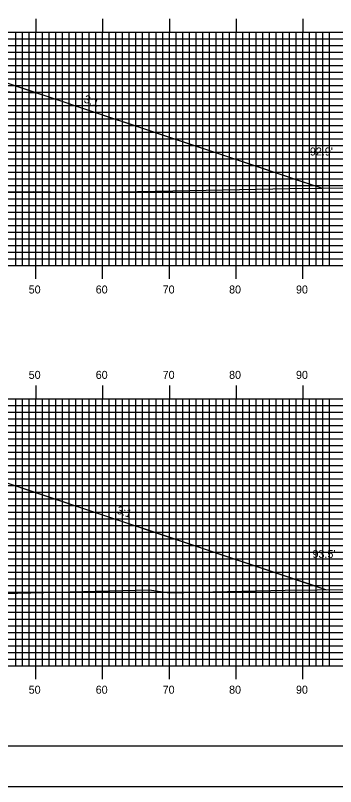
# Model space of a CAD drawing. Extents: x 1756282 to 1756625, y 442591 to 442811.
# Drawn here: x 1756494.5 to 1756542.5, y 442590.5 to 442706.2 of the extents above; entities that cross this region are included whole.
import ezdxf

# ---------------------------------------------------------------- set-up
doc = ezdxf.new("R2010")
doc.units = 0
for name, color, linetype in [('ANNOTATION', 7, 'Continuous'), ('BORDER', 7, 'Continuous'), ('D_Roadway_Centerline', 7, 'Continuous'), ('D_Roadway_SlopeLines', 7, 'Continuous'), ('D_Roadway_SubGrade', 7, 'Continuous'), ('D_Text_Standard', 7, 'Continuous'), ('H_V ANNOTATION', 7, 'Continuous'), ('MAJOR', 7, 'Continuous'), ('MINOR', 7, 'Continuous'), ('PLOT BOUNDARY', 7, 'Continuous'), ('S_Roadway_Centerline', 7, 'Continuous')]:
    doc.layers.add(name, color=color, linetype=linetype)

msp = doc.modelspace()

# ---------------------------------------------------------------- linework, layer by layer
at = {"layer": 'BORDER'}
msp.add_lwpolyline([(1756297.97, 442596.67), (1756617.97, 442596.67), (1756617.97, 442806.67), (1756297.97, 442806.67)], close=True, dxfattribs=at)
at = {"layer": 'D_Roadway_Centerline'}
for points in [[(1756489.74, 442697.22), (1756497.1, 442694.76), (1756497.82, 442694.52), (1756499.66, 442693.9), (1756500.24, 442693.71), (1756509.89, 442690.48), (1756510.11, 442690.41), (1756510.64, 442690.23), (1756510.77, 442690.19), (1756511.07, 442690.09), (1756515.9, 442688.47), (1756522.47, 442686.28), (1756522.59, 442686.23), (1756522.68, 442686.21), (1756531.54, 442683.25), (1756533.88, 442682.46), (1756535.28, 442681.99), (1756535.47, 442681.93), (1756540.47, 442680.26)], [(1756494.45, 442635.67), (1756495.01, 442635.48), (1756495.26, 442635.4), (1756509.79, 442630.54), (1756516.57, 442628.27), (1756524.29, 442625.68), (1756537.31, 442621.32), (1756538.5, 442620.93), (1756541.12, 442620.05)]]:
    msp.add_lwpolyline(points, dxfattribs=at)
at = {"layer": 'D_Roadway_SlopeLines'}
for points in [[(1756489.74, 442697.22), (1756540.47, 442680.26)], [(1756485.73, 442638.59), (1756541.12, 442620.05)]]:
    msp.add_lwpolyline(points, dxfattribs=at)
at = {"layer": 'D_Roadway_SubGrade'}
msp.add_lwpolyline([(1756478.7, 442697.01), (1756478.7, 442697.43), (1756489.74, 442696.97), (1756489.74, 442697.22), (1756497.82, 442694.52), (1756478.7, 442695.18)], close=True, dxfattribs=at)
at = {"layer": 'MAJOR'}
for p, q in [((1756497.57, 442705.67), (1756497.57, 442703.67)), ((1756507.57, 442705.67), (1756507.57, 442703.67)), ((1756517.57, 442705.67), (1756517.57, 442703.67)), ((1756527.57, 442705.67), (1756527.57, 442703.67)), ((1756537.57, 442705.67), (1756537.57, 442703.67)), ((1756307.57, 442703.67), (1756587.57, 442703.67)), ((1756307.57, 442703.67), (1756587.57, 442703.67)), ((1756497.57, 442668.67), (1756497.57, 442703.67)), ((1756507.57, 442668.67), (1756507.57, 442703.67)), ((1756517.57, 442668.67), (1756517.57, 442703.67)), ((1756527.57, 442668.67), (1756527.57, 442703.67)), ((1756537.57, 442668.67), (1756537.57, 442703.67)), ((1756307.57, 442698.67), (1756587.57, 442698.67)), ((1756307.57, 442693.67), (1756587.57, 442693.67)), ((1756307.57, 442688.67), (1756587.57, 442688.67)), ((1756307.57, 442683.67), (1756587.57, 442683.67)), ((1756307.57, 442678.67), (1756587.57, 442678.67)), ((1756307.57, 442673.67), (1756587.57, 442673.67)), ((1756307.57, 442668.67), (1756587.57, 442668.67)), ((1756307.57, 442668.67), (1756587.57, 442668.67)), ((1756497.57, 442666.66), (1756497.57, 442668.67)), ((1756507.57, 442666.66), (1756507.57, 442668.67)), ((1756517.57, 442666.66), (1756517.57, 442668.67)), ((1756527.57, 442666.66), (1756527.57, 442668.67)), ((1756537.57, 442666.66), (1756537.57, 442668.67)), ((1756497.57, 442650.67), (1756497.57, 442648.67)), ((1756507.57, 442650.67), (1756507.57, 442648.67)), ((1756517.57, 442650.67), (1756517.57, 442648.67)), ((1756527.57, 442650.67), (1756527.57, 442648.67)), ((1756537.57, 442650.67), (1756537.57, 442648.67)), ((1756307.57, 442648.67), (1756587.57, 442648.67)), ((1756307.57, 442648.67), (1756587.57, 442648.67)), ((1756497.57, 442608.67), (1756497.57, 442648.67)), ((1756507.57, 442608.67), (1756507.57, 442648.67)), ((1756517.57, 442608.67), (1756517.57, 442648.67)), ((1756527.57, 442608.67), (1756527.57, 442648.67)), ((1756537.57, 442608.67), (1756537.57, 442648.67)), ((1756307.57, 442643.67), (1756587.57, 442643.67)), ((1756307.57, 442638.67), (1756587.57, 442638.67)), ((1756307.57, 442633.67), (1756587.57, 442633.67)), ((1756307.57, 442628.67), (1756587.57, 442628.67)), ((1756307.57, 442623.67), (1756587.57, 442623.67)), ((1756307.57, 442618.67), (1756587.57, 442618.67)), ((1756307.57, 442613.67), (1756587.57, 442613.67)), ((1756307.57, 442608.67), (1756587.57, 442608.67)), ((1756307.57, 442608.67), (1756587.57, 442608.67)), ((1756497.57, 442606.66), (1756497.57, 442608.67)), ((1756507.57, 442606.66), (1756507.57, 442608.67)), ((1756517.57, 442606.66), (1756517.57, 442608.67)), ((1756527.57, 442606.66), (1756527.57, 442608.67)), ((1756537.57, 442606.66), (1756537.57, 442608.67))]:
    msp.add_line(p, q, dxfattribs=at)
at = {"layer": 'MINOR'}
for p, q in [((1756494.57, 442668.67), (1756494.57, 442703.67)), ((1756495.57, 442668.67), (1756495.57, 442703.67)), ((1756496.57, 442668.67), (1756496.57, 442703.67)), ((1756498.57, 442668.67), (1756498.57, 442703.67)), ((1756499.57, 442668.67), (1756499.57, 442703.67)), ((1756500.57, 442668.67), (1756500.57, 442703.67)), ((1756501.57, 442668.67), (1756501.57, 442703.67)), ((1756502.57, 442668.67), (1756502.57, 442703.67)), ((1756503.57, 442668.67), (1756503.57, 442703.67)), ((1756504.57, 442668.67), (1756504.57, 442703.67)), ((1756505.57, 442668.67), (1756505.57, 442703.67)), ((1756506.57, 442668.67), (1756506.57, 442703.67)), ((1756508.57, 442668.67), (1756508.57, 442703.67)), ((1756509.57, 442668.67), (1756509.57, 442703.67)), ((1756510.57, 442668.67), (1756510.57, 442703.67)), ((1756511.57, 442668.67), (1756511.57, 442703.67)), ((1756512.57, 442668.67), (1756512.57, 442703.67)), ((1756513.57, 442668.67), (1756513.57, 442703.67)), ((1756514.57, 442668.67), (1756514.57, 442703.67)), ((1756515.57, 442668.67), (1756515.57, 442703.67)), ((1756516.57, 442668.67), (1756516.57, 442703.67)), ((1756518.57, 442668.67), (1756518.57, 442703.67)), ((1756519.57, 442668.67), (1756519.57, 442703.67)), ((1756520.57, 442668.67), (1756520.57, 442703.67)), ((1756521.57, 442668.67), (1756521.57, 442703.67)), ((1756522.57, 442668.67), (1756522.57, 442703.67)), ((1756523.57, 442668.67), (1756523.57, 442703.67)), ((1756524.57, 442668.67), (1756524.57, 442703.67)), ((1756525.57, 442668.67), (1756525.57, 442703.67)), ((1756526.57, 442668.67), (1756526.57, 442703.67)), ((1756528.57, 442668.67), (1756528.57, 442703.67)), ((1756529.57, 442668.67), (1756529.57, 442703.67)), ((1756530.57, 442668.67), (1756530.57, 442703.67)), ((1756531.57, 442668.67), (1756531.57, 442703.67)), ((1756532.57, 442668.67), (1756532.57, 442703.67)), ((1756533.57, 442668.67), (1756533.57, 442703.67)), ((1756534.57, 442668.67), (1756534.57, 442703.67)), ((1756535.57, 442668.67), (1756535.57, 442703.67)), ((1756536.57, 442668.67), (1756536.57, 442703.67)), ((1756538.57, 442668.67), (1756538.57, 442703.67)), ((1756539.57, 442668.67), (1756539.57, 442703.67)), ((1756540.57, 442668.67), (1756540.57, 442703.67)), ((1756541.57, 442668.67), (1756541.57, 442703.67)), ((1756307.57, 442702.67), (1756587.57, 442702.67)), ((1756307.57, 442701.67), (1756587.57, 442701.67)), ((1756307.57, 442700.67), (1756587.57, 442700.67)), ((1756307.57, 442699.67), (1756587.57, 442699.67)), ((1756307.57, 442697.67), (1756587.57, 442697.67)), ((1756307.57, 442696.67), (1756587.57, 442696.67)), ((1756307.57, 442695.67), (1756587.57, 442695.67)), ((1756307.57, 442694.67), (1756587.57, 442694.67)), ((1756307.57, 442692.67), (1756587.57, 442692.67)), ((1756307.57, 442691.67), (1756587.57, 442691.67)), ((1756307.57, 442690.67), (1756587.57, 442690.67)), ((1756307.57, 442689.67), (1756587.57, 442689.67)), ((1756307.57, 442687.67), (1756587.57, 442687.67)), ((1756307.57, 442686.67), (1756587.57, 442686.67)), ((1756307.57, 442685.67), (1756587.57, 442685.67)), ((1756307.57, 442684.67), (1756587.57, 442684.67)), ((1756307.57, 442682.67), (1756587.57, 442682.67)), ((1756307.57, 442681.67), (1756587.57, 442681.67)), ((1756307.57, 442680.67), (1756587.57, 442680.67)), ((1756307.57, 442679.67), (1756587.57, 442679.67)), ((1756307.57, 442677.67), (1756587.57, 442677.67)), ((1756307.57, 442676.67), (1756587.57, 442676.67)), ((1756307.57, 442675.67), (1756587.57, 442675.67)), ((1756307.57, 442674.67), (1756587.57, 442674.67)), ((1756307.57, 442672.67), (1756587.57, 442672.67)), ((1756307.57, 442671.67), (1756587.57, 442671.67)), ((1756307.57, 442670.67), (1756587.57, 442670.67)), ((1756307.57, 442669.67), (1756587.57, 442669.67)), ((1756494.57, 442608.67), (1756494.57, 442648.67)), ((1756495.57, 442608.67), (1756495.57, 442648.67)), ((1756496.57, 442608.67), (1756496.57, 442648.67)), ((1756498.57, 442608.67), (1756498.57, 442648.67)), ((1756499.57, 442608.67), (1756499.57, 442648.67)), ((1756500.57, 442608.67), (1756500.57, 442648.67)), ((1756501.57, 442608.67), (1756501.57, 442648.67)), ((1756502.57, 442608.67), (1756502.57, 442648.67)), ((1756503.57, 442608.67), (1756503.57, 442648.67)), ((1756504.57, 442608.67), (1756504.57, 442648.67)), ((1756505.57, 442608.67), (1756505.57, 442648.67)), ((1756506.57, 442608.67), (1756506.57, 442648.67)), ((1756508.57, 442608.67), (1756508.57, 442648.67)), ((1756509.57, 442608.67), (1756509.57, 442648.67)), ((1756510.57, 442608.67), (1756510.57, 442648.67)), ((1756511.57, 442608.67), (1756511.57, 442648.67)), ((1756512.57, 442608.67), (1756512.57, 442648.67)), ((1756513.57, 442608.67), (1756513.57, 442648.67)), ((1756514.57, 442608.67), (1756514.57, 442648.67)), ((1756515.57, 442608.67), (1756515.57, 442648.67)), ((1756516.57, 442608.67), (1756516.57, 442648.67)), ((1756518.57, 442608.67), (1756518.57, 442648.67)), ((1756519.57, 442608.67), (1756519.57, 442648.67)), ((1756520.57, 442608.67), (1756520.57, 442648.67)), ((1756521.57, 442608.67), (1756521.57, 442648.67)), ((1756522.57, 442608.67), (1756522.57, 442648.67)), ((1756523.57, 442608.67), (1756523.57, 442648.67)), ((1756524.57, 442608.67), (1756524.57, 442648.67)), ((1756525.57, 442608.67), (1756525.57, 442648.67)), ((1756526.57, 442608.67), (1756526.57, 442648.67)), ((1756528.57, 442608.67), (1756528.57, 442648.67)), ((1756529.57, 442608.67), (1756529.57, 442648.67)), ((1756530.57, 442608.67), (1756530.57, 442648.67)), ((1756531.57, 442608.67), (1756531.57, 442648.67)), ((1756532.57, 442608.67), (1756532.57, 442648.67)), ((1756533.57, 442608.67), (1756533.57, 442648.67)), ((1756534.57, 442608.67), (1756534.57, 442648.67)), ((1756535.57, 442608.67), (1756535.57, 442648.67)), ((1756536.57, 442608.67), (1756536.57, 442648.67)), ((1756538.57, 442608.67), (1756538.57, 442648.67)), ((1756539.57, 442608.67), (1756539.57, 442648.67)), ((1756540.57, 442608.67), (1756540.57, 442648.67)), ((1756541.57, 442608.67), (1756541.57, 442648.67)), ((1756307.57, 442647.67), (1756587.57, 442647.67)), ((1756307.57, 442646.67), (1756587.57, 442646.67)), ((1756307.57, 442645.67), (1756587.57, 442645.67)), ((1756307.57, 442644.67), (1756587.57, 442644.67)), ((1756307.57, 442642.67), (1756587.57, 442642.67)), ((1756307.57, 442641.67), (1756587.57, 442641.67)), ((1756307.57, 442640.67), (1756587.57, 442640.67)), ((1756307.57, 442639.67), (1756587.57, 442639.67)), ((1756307.57, 442637.67), (1756587.57, 442637.67)), ((1756307.57, 442636.67), (1756587.57, 442636.67)), ((1756307.57, 442635.67), (1756587.57, 442635.67)), ((1756307.57, 442634.67), (1756587.57, 442634.67)), ((1756307.57, 442632.67), (1756587.57, 442632.67)), ((1756307.57, 442631.67), (1756587.57, 442631.67)), ((1756307.57, 442630.67), (1756587.57, 442630.67)), ((1756307.57, 442629.67), (1756587.57, 442629.67)), ((1756307.57, 442627.67), (1756587.57, 442627.67)), ((1756307.57, 442626.67), (1756587.57, 442626.67)), ((1756307.57, 442625.67), (1756587.57, 442625.67)), ((1756307.57, 442624.67), (1756587.57, 442624.67)), ((1756307.57, 442622.67), (1756587.57, 442622.67)), ((1756307.57, 442621.67), (1756587.57, 442621.67)), ((1756307.57, 442620.67), (1756587.57, 442620.67)), ((1756307.57, 442619.67), (1756587.57, 442619.67)), ((1756307.57, 442617.67), (1756587.57, 442617.67)), ((1756307.57, 442616.67), (1756587.57, 442616.67)), ((1756307.57, 442615.67), (1756587.57, 442615.67)), ((1756307.57, 442614.67), (1756587.57, 442614.67)), ((1756307.57, 442612.67), (1756587.57, 442612.67)), ((1756307.57, 442611.67), (1756587.57, 442611.67)), ((1756307.57, 442610.67), (1756587.57, 442610.67)), ((1756307.57, 442609.67), (1756587.57, 442609.67))]:
    msp.add_line(p, q, dxfattribs=at)
at = {"layer": 'PLOT BOUNDARY'}
msp.add_lwpolyline([(1756281.78, 442590.55), (1756621.78, 442590.55), (1756621.78, 442810.55), (1756281.78, 442810.55)], close=True, dxfattribs=at)
at = {"layer": 'S_Roadway_Centerline'}
for points in [[(1756398.08, 442679.98), (1756402.56, 442679.91), (1756404.87, 442679.86), (1756422.76, 442679.94), (1756444.5, 442679.93), (1756448.72, 442680.09), (1756452.91, 442680.01), (1756471.12, 442680.02), (1756493.51, 442679.73), (1756497.21, 442679.76), (1756504.87, 442679.61), (1756518.11, 442679.86), (1756535.57, 442680.21), (1756550.37, 442680.37), (1756550.69, 442680.4), (1756556.7, 442680.11), (1756579.05, 442679.06), (1756581.27, 442678.69), (1756582.24, 442677.83), (1756586.52, 442675.15), (1756587.57, 442675.15)], [(1756307.57, 442618.08), (1756314.44, 442618.16), (1756314.67, 442617.91), (1756326.37, 442617.54), (1756331.28, 442617.49), (1756351.52, 442618.67), (1756360.56, 442619.11), (1756369.53, 442619.26), (1756401.49, 442619.32), (1756415.22, 442619.96), (1756421.47, 442620.05), (1756445.66, 442619.4), (1756471.4, 442619.4), (1756485.64, 442619.61), (1756486.6, 442619.72), (1756492.85, 442619.49), (1756514.56, 442620.04), (1756517.59, 442619.61), (1756534.91, 442619.98), (1756554.07, 442620.19), (1756568.96, 442620.31), (1756579.7, 442620.36), (1756585.04, 442620.35), (1756587.57, 442620.19)]]:
    msp.add_lwpolyline(points, dxfattribs=at)

# ---------------------------------------------------------------- texts
at = {"layer": 'ANNOTATION'}
for rotation, p in [(341.5155, (1756504.67, 442693.14)), (341.4897, (1756509.58, 442631.52))]:
    msp.add_text('3:1', height=1.2, rotation=rotation, dxfattribs=at).set_placement(p)
at = {"layer": 'D_Text_Standard'}
for s, p in [("92.9'", (1756538.63, 442685.16)), ("93.5'", (1756539.02, 442624.82))]:
    msp.add_text(s, height=1.2, dxfattribs=at).set_placement(p)
at = {"layer": 'H_V ANNOTATION'}
for s, p in [('50', (1756496.5, 442664.47)), ('60', (1756506.54, 442664.47)), ('70', (1756516.57, 442664.47)), ('80', (1756526.52, 442664.47)), ('90', (1756536.54, 442664.47)), ('50', (1756496.5, 442651.67)), ('60', (1756506.54, 442651.67)), ('70', (1756516.57, 442651.67)), ('80', (1756526.52, 442651.67)), ('90', (1756536.54, 442651.67)), ('50', (1756496.5, 442604.47)), ('60', (1756506.54, 442604.47)), ('70', (1756516.57, 442604.47)), ('80', (1756526.52, 442604.47)), ('90', (1756536.54, 442604.47))]:
    msp.add_text(s, height=1.2, dxfattribs=at).set_placement(p)

doc.saveas('drawing.dxf')
